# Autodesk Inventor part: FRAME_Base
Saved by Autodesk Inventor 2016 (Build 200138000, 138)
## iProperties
Created: 2016-03
Part Number: FRAME_Base
Material: Generic
Document SubType Name: Modeling
Designer: bongo_000
Density: 1 g/cm^3
Appearance: Default
Author: bongo_000
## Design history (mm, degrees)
feature "SOLID1"
body "Solid1"
